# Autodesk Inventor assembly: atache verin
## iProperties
Shininess: 41.0
Length Units: 11269
Angle Units: 11279
Time Units: 11290
Mass Units: 11283
Length Display Precision: 3
Angle Display Precision: 2
Created: 2002-05
Part Number: atache verin
Document SubType Name: Assemblage
Designer: REVEST Pierre
Density: 0.0
Volumn: 0.0
Area: 0.0
PropertySet Name: Model Information
Control State: 0
Master: False
Checked Out: False
Author: REVEST Pierre
